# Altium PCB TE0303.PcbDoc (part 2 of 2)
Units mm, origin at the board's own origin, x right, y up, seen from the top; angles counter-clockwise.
Board outline 115 x 70 mm, 4 copper layers (L 01 (Top), L 02, L 03, L 04 (Bot)), stack 1.564 mm thick; 42 components, 141 nets, 429 pads, 134 vias.
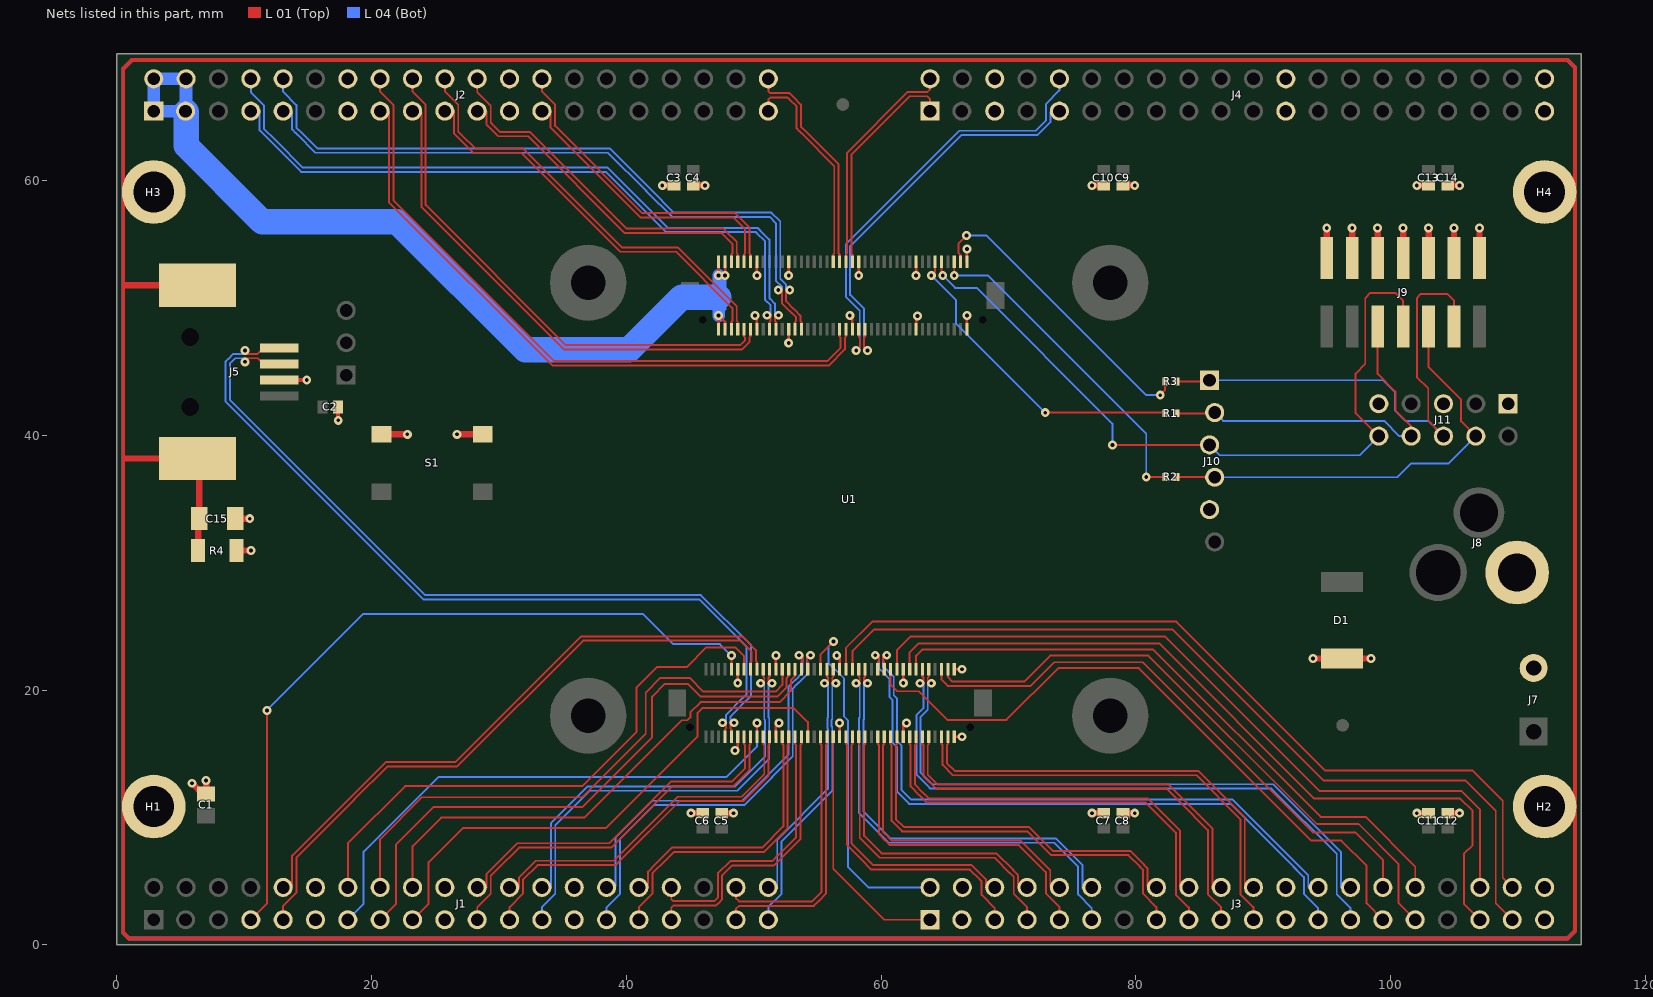
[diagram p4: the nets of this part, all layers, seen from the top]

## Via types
v1: diameter 0.7, hole 0.3, L 01 (Top) to L 04 (Bot), 134 vias

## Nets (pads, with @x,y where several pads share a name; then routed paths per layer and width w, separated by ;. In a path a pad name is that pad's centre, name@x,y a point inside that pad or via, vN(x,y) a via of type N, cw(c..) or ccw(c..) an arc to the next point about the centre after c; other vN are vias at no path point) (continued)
B0_L23_N: J2.9 U1.J4-25 | length 52.7
  L 01 (Top) w0.15: v1(51.93,51.429) 52.21,51.429 52.21,50.409 52.885,49.734 52.984,49.635 53.33,49.289 53.33,49.005 53.25,48.925 U1.J4-25@53.25,48.35
  L 04 (Bot) w0.15: J2.9@13.05,65.48 13.695,65.48 13.75,65.425 13.75,64.05 14.05,63.75 14.15,63.65 15.59,62.21 38.559,62.21 41.56,59.209 41.659,59.11 43.594,57.175 51.25,57.175 51.75,56.675 51.75,52.175 52.21,51.715 52.21,51.429 v1(51.93,51.429)
B0_L23_P: J2.10 U1.J4-27 | length 55
  L 01 (Top) w0.15: v1(52.83,51.429) 52.55,51.429 52.55,50.55 53.125,49.975 53.225,49.875 53.67,49.43 53.67,49.005 53.75,48.925 U1.J4-27@53.75,48.35
  L 04 (Bot) w0.15: J2.10@13.05,68.02 13.05,67 14.09,65.96 14.09,64.191 14.291,63.99 14.39,63.891 15.731,62.55 38.7,62.55 41.8,59.45 41.9,59.35 43.735,57.515 51.391,57.515 52.09,56.816 52.09,52.316 52.55,51.856 52.55,51.429 v1(52.83,51.429)
B0_L24_N: J2.7 U1.J4-17 | length 52.9
  L 01 (Top) w0.15: U1.J4-17@51.25,48.35 51.25,48.925 51.33,49.005 v1@51.33,49.45
  L 04 (Bot) w0.15: J2.7@10.51,65.48 11.195,65.48 11.2,65.475 11.2,63.975 12.175,63 12.275,62.9 14.465,60.71 38.384,60.71 43.119,55.975 50.175,55.975 50.25,55.9 50.9,55.25 50.9,50.65 51,50.55 51.05,50.5 51.33,50.22 51.33,49.45 v1(51.05,49.45)
B0_L24_P: J2.8 U1.J4-19 | length 55.2
  L 01 (Top) w0.15: v1@51.67,49.45 51.67,49.005 51.75,48.925 U1.J4-19@51.75,48.35
  L 04 (Bot) w0.15: J2.8@10.51,68.02 10.51,66.965 11.54,65.935 11.54,64.116 12.416,63.24 12.515,63.141 14.606,61.05 38.525,61.05 43.26,56.315 50.316,56.315 50.415,56.215 50.49,56.141 51.24,55.391 51.24,50.791 51.29,50.741 51.67,50.361 51.67,49.45 v1(51.95,49.45)
B2_GCLK13: J3.1 U1.J5-41 | length 19.6
  L 01 (Top) w0.15: U1.J5-41@56.25,16.35 56.25,5.975 60.245,1.98 J3.1@63.85,1.98
B2_GCLK_L13_N: J3.7 U1.J5-49 | length 25.2
  L 01 (Top) w0.15: U1.J5-49@58.25,16.35 58.25,15.775 58.33,15.695 ; 58.33,15.72 58.33,15.695 ; J3.7@71.47,1.98 71.47,2.98 70.425,4.025 70.425,5.35 70.225,5.55 70.125,5.65 68.925,6.85 59.9,6.85 59.8,6.95 58.33,8.42 58.33,15.695
B2_GCLK_L13_P: J3.8 U1.J5-51 | length 22.8
  L 01 (Top) w0.15: U1.J5-51@58.75,16.35 58.75,15.775 58.67,15.695 58.67,8.561 60.041,7.19 69.066,7.19 70.366,5.89 70.465,5.791 70.765,5.491 70.765,4.56 70.805,4.52 J3.8@71.47,4.52
B2_IO_L03: J1.15 U1.J5-28 | length 46.4
  L 01 (Top) w0.15: J1.15@20.67,1.98 21.925,3.235 21.925,7.9 24.875,10.85 36.575,10.85 42.025,16.3 42.025,19.5 43.025,20.5 44.825,20.5 45.374,19.951 45.825,19.5 51.85,19.5 52.59,20.24 52.59,20.965 52.75,21.125 U1.J5-28@52.75,21.65
B2_IO_P9: J3.29 U1.J5-60 | length 52.6
  L 01 (Top) w0.15: U1.J5-60@60.75,21.65 60.75,20.45 61.275,19.925 62.95,19.925 65.2,17.675 69.85,17.675 73.925,21.75 80.25,21.75 93.8,8.2 96.15,8.2 98.125,6.225 98.125,3.265 J3.29@99.41,1.98
B2_IO_P10: J3.35 U1.J5-66 | length 60.6
  L 01 (Top) w0.15: U1.J5-66@62.25,21.65 62.25,22.975 62.95,23.675 81.85,23.675 94.025,11.5 105.475,11.5 106.45,10.525 106.45,7.825 105.775,7.15 105.775,3.235 J3.35@107.03,1.98
B2_IO_R9: J3.32 U1.J5-68 | length 49.2
  L 01 (Top) w0.15: U1.J5-68@62.75,21.65 62.75,22.725 63.225,23.2 81.375,23.2 94.525,10.05 98.05,10.05 101.95,6.15 J3.32@101.95,4.52
B2_IO_R11: J3.36 U1.J5-62 | length 59.5
  L 01 (Top) w0.15: U1.J5-62@61.25,21.65 61.25,23.15 62.325,24.225 82.3,24.225 94.425,12.1 105.575,12.1 107.03,10.645 J3.36@107.03,4.52
B2_IO_U5: J1.18 U1.J5-30 | length 40.1
  L 01 (Top) w0.15: J1.18@23.21,4.52 23.21,7.76 25.45,10 36.7,10 44.35,17.65 44.8,17.65 45.025,17.875 45.025,18.275 45.825,19.075 52.05,19.075 52.93,19.955 52.93,20.805 53.25,21.125 U1.J5-30@53.25,21.65
B2_IO_U6: J3.2 U1.J5-38 | length 28.2
  L 01 (Top) w0.15: U1.J5-38@55.25,21.65 55.25,22.825 56.25,23.825 v1(56.275,23.825)
  L 04 (Bot) w0.15: v1(56.275,23.825) 55.875,23.425 55.875,22.15 57.093,20.932 57.093,17.957 57.4,17.65 57.4,6.125 59.005,4.52 J3.2@63.85,4.52
B2_IO_U13: J3.31 U1.J5-78 | length 48.7
  L 01 (Top) w0.15: U1.J5-78@65.25,21.65 65.25,21.05 65.61,20.69 71.24,20.69 73.275,22.725 81,22.725 94.225,9.5 97.5,9.5 100.65,6.35 100.65,3.28 J3.31@101.95,1.98
B2_IO_V7: J1.17 U1.J5-33 | length 42.5
  L 01 (Top) w0.15: J1.17@23.21,1.98 24.475,3.245 24.475,6.5 27.175,9.2 38.425,9.2 45.6,16.375 45.6,18.225 46,18.625 53.125,18.625 54.25,17.5 U1.J5-33@54.25,16.35
B2_IP_T7: J3.38 U1.J5-46 | length 67.1
  L 01 (Top) w0.15: U1.J5-46@57.25,21.65 57.25,23.325 59.325,25.4 83.2,25.4 94.9,13.7 106.45,13.7 108.825,11.325 108.825,5.265 J3.38@109.57,4.52
B2_IP_U8: J3.37 U1.J5-48 | length 67.6
  L 01 (Top) w0.15: U1.J5-48@57.75,21.65 57.75,23.05 59.475,24.775 82.875,24.775 94.75,12.9 105.9,12.9 108.275,10.525 108.275,3.275 J3.37@109.57,1.98
B2_IP_V4: J1.13 U1.J5-17 | length 43.1
  L 01 (Top) w0.15: U1.J5-17@50.25,16.35 v1(50.25,17.425)
  L 04 (Bot) w0.15: J1.13@18.13,1.98 19.375,3.225 19.375,7.325 25.25,13.2 47.875,13.2 50.25,15.575 v1(50.25,17.425)
B2_IP_V14: J3.30 U1.J5-76 | length 45
  L 01 (Top) w0.15: U1.J5-76@64.75,21.65 64.75,20.825 65.225,20.35 71.75,20.35 73.6,22.2 80.55,22.2 93.925,8.825 97.275,8.825 99.41,6.69 J3.30@99.41,4.52
B2_L04_N: J1.32 U1.J5-25 | length 21.1
  L 01 (Top) w0.15: J1.32@40.99,4.52 40.995,4.525 41.71,4.525 41.71,5.766 42.285,6.341 42.384,6.44 43.584,7.64 50.659,7.64 52.33,9.311 52.33,15.695 52.25,15.775 U1.J5-25@52.25,16.35
B2_L04_P: J1.31 U1.J5-27 | length 23.4
  L 01 (Top) w0.15: J1.31@40.99,1.98 40.99,2.965 42.05,4.025 42.05,5.625 42.525,6.1 42.625,6.2 43.725,7.3 50.8,7.3 52.67,9.17 52.67,15.695 52.75,15.775 U1.J5-27@52.75,16.35
B2_L05_N: J1.33 U1.J5-31 | length 22.5
  L 01 (Top) w0.15: J1.33@43.53,1.98 43.53,2.93 43.7,3.1 46.225,3.1 47.05,3.1 47.15,3.2 47.2,3.25 47.525,3.575 47.525,5.475 48.3,6.25 51.6,6.25 52.15,6.8 52.25,6.9 53.67,8.32 53.67,15.695 53.75,15.775 U1.J5-31@53.75,16.35
B2_L05_P: J1.34 U1.J5-29 | length 21.9
  L 01 (Top) w0.15: J1.34@43.53,4.52 43.53,3.61 43.7,3.44 46.225,3.44 46.909,3.44 46.959,3.49 47.185,3.716 47.185,5.616 48.159,6.59 51.459,6.59 51.91,7.041 52.009,7.14 53.33,8.461 53.33,15.695 53.25,15.775 U1.J5-29@53.25,16.35
B2_L06_N: J1.29 U1.J5-34 | length 32.8
  L 01 (Top) w0.15: v1@54.17,22.75 54.17,22.305 54.25,22.225 U1.J5-34@54.25,21.65
  L 04 (Bot) w0.15: J1.29@38.45,1.98 38.45,2.95 39.49,3.99 39.49,8.305 42.17,10.985 49.241,10.985 51.441,13.185 51.54,13.284 53.065,14.809 53.065,20.134 53.391,20.46 53.49,20.559 54.17,21.239 54.17,22.75 v1(54.45,22.75)
B2_L06_P: J1.30 U1.J5-32 | length 30.5
  L 01 (Top) w0.15: U1.J5-32@53.75,21.65 53.75,22.225 53.83,22.305 v1@53.83,22.75
  L 04 (Bot) w0.15: J1.30@38.45,4.52 39.07,4.52 39.15,4.6 39.15,8.445 42.03,11.325 49.1,11.325 51.2,13.425 51.3,13.525 52.725,14.95 52.725,20.275 53.15,20.7 53.25,20.8 53.83,21.38 53.83,22.75 v1(53.55,22.75)
B2_L07_N: J1.38 U1.J5-37 | length 20.2
  L 01 (Top) w0.15: J1.38@48.61,4.52 48.61,3.655 48.85,3.415 54.584,3.415 54.76,3.591 54.859,3.69 55.33,4.161 55.33,15.695 55.25,15.775 U1.J5-37@55.25,16.35
B2_L07_P: J1.37 U1.J5-39 | length 20.8
  L 01 (Top) w0.15: J1.37@48.61,1.98 48.61,2.835 48.85,3.075 54.725,3.075 55,3.35 55.1,3.45 55.67,4.02 55.67,15.695 55.75,15.775 U1.J5-39@55.75,16.35
B2_L09_N: J3.26 U1.J5-58 | length 49
  L 01 (Top) w0.15: v1@60.17,22.75 60.17,22.305 60.25,22.225 U1.J5-58@60.25,21.65
  L 04 (Bot) w0.15: v1(60.45,22.75) 60.17,22.75 60.17,21.88 60.525,21.525 60.625,21.425 61,21.05 61,19.625 61.25,19.375 61.25,16.025 61.6,15.675 61.6,12.175 62.35,11.425 87.6,11.425 92.525,6.5 93.55,5.475 93.55,4.575 93.605,4.52 J3.26@94.33,4.52
B2_L09_P: J3.25 U1.J5-56 | length 52
  L 01 (Top) w0.15: U1.J5-56@59.75,21.65 59.75,22.225 59.83,22.305 v1@59.83,22.75
  L 04 (Bot) w0.15: v1(59.55,22.75) 59.83,22.75 59.83,21.739 60.285,21.284 60.384,21.185 60.66,20.909 60.66,19.484 60.91,19.234 60.91,15.885 61.26,15.535 61.26,12.034 62.209,11.085 87.459,11.085 92.005,6.539 ; 92.285,6.26 92.005,6.539 ; 92.384,6.16 93.21,5.334 93.21,4.015 94.33,2.895 J3.25@94.33,1.98 ; 92.646,5.898 92.005,6.539
B2_L10_N: J3.5 U1.J5-45 | length 23.7
  L 01 (Top) w0.15: U1.J5-45@57.25,16.35 57.25,15.775 57.33,15.695 57.33,7.845 58.3,6.875 58.4,6.775 59.25,5.925 66.975,5.925 67.75,5.15 67.85,5.05 67.9,5 67.9,3.925 68.93,2.895 J3.5@68.93,1.98
B2_L10_P: J3.6 U1.J5-47 | length 21.4
  L 01 (Top) w0.15: U1.J5-47@57.75,16.35 57.75,15.775 57.67,15.695 57.67,7.986 58.541,7.115 58.64,7.016 59.391,6.265 67.116,6.265 67.991,5.39 68.09,5.291 68.25,5.131 68.25,4.6 68.33,4.52 J3.6@68.93,4.52
B2_L18_N: J3.9 U1.J5-55 | length 26.2
  L 01 (Top) w0.15: U1.J5-55@59.75,16.35 59.75,15.775 59.83,15.695 59.83,8.72 60.35,8.2 60.45,8.1 60.7,7.85 70.825,7.85 72.95,5.725 72.95,4.05 74.01,2.99 J3.9@74.01,1.98
B2_L18_P: J3.10 U1.J5-57 | length 23.9
  L 01 (Top) w0.15: U1.J5-57@60.25,16.35 60.25,15.775 60.17,15.695 60.17,8.861 60.591,8.44 60.69,8.341 60.841,8.19 70.966,8.19 73.29,5.866 73.29,4.59 73.36,4.52 J3.10@74.01,4.52
B2_L19_N: J3.17 U1.J5-65 | length 33.5
  L 01 (Top) w0.15: U1.J5-65@62.25,16.35 62.25,15.775 62.33,15.695 62.33,12.445 63.05,11.725 63.15,11.625 63.6,11.175 80.8,11.175 83.15,8.825 83.15,3.95 84.17,2.93 J3.17@84.17,1.98
B2_L19_P: J3.18 U1.J5-67 | length 31.2
  L 01 (Top) w0.15: U1.J5-67@62.75,16.35 62.75,15.775 62.67,15.695 62.67,12.586 63.291,11.965 63.39,11.866 63.741,11.515 80.941,11.515 83.49,8.966 83.49,4.59 83.56,4.52 J3.18@84.17,4.52
B2_L20_N: J3.15 U1.J5-59 | length 32.4
  L 01 (Top) w0.15: U1.J5-59@60.75,16.35 60.75,15.775 60.83,15.695 ; 60.83,15.72 60.83,15.695 ; J3.15@81.63,1.98 81.63,2.97 80.575,4.025 80.575,5.9 80.45,6.025 80.35,6.125 79.425,7.05 73.35,7.05 72.9,7.5 72.8,7.6 71.475,8.925 61.65,8.925 60.83,9.745 60.83,15.695
B2_L20_P: J3.16 U1.J5-61 | length 30
  L 01 (Top) w0.15: U1.J5-61@61.25,16.35 61.25,15.775 61.17,15.695 61.17,9.886 61.791,9.265 71.616,9.265 73.041,7.84 73.14,7.741 73.491,7.39 79.566,7.39 80.591,6.365 80.69,6.266 80.915,6.041 80.915,4.56 80.955,4.52 J3.16@81.63,4.52
B2_L21_N: J3.27 U1.J5-70 | length 50.2
  L 01 (Top) w0.15: U1.J5-70@63.25,21.65 63.25,21.075 63.33,20.995 v1@63.33,20.55
  L 04 (Bot) w0.15: v1(63.05,20.55) 63.33,20.55 63.33,18.605 62.775,18.05 62.775,13.394 63.56,12.609 63.659,12.51 63.884,12.285 90.659,12.285 95.785,7.159 95.785,6.025 ; 95.785,6.25 95.785,3.965 96.87,2.88 J3.27@96.87,1.98
B2_L21_P: J3.28 U1.J5-72 | length 47.8
  L 01 (Top) w0.15: v1@63.67,20.55 63.67,20.995 63.75,21.075 U1.J5-72@63.75,21.65
  L 04 (Bot) w0.15: v1(63.95,20.55) 63.67,20.55 63.67,18.464 63.115,17.909 63.115,13.535 63.8,12.85 63.9,12.75 64.025,12.625 90.8,12.625 96.125,7.3 96.125,6.025 96.125,4.525 96.13,4.52 J3.28@96.87,4.52
B2_L22_N: J3.19 U1.J5-69 | length 34.7
  L 01 (Top) w0.15: U1.J5-69@63.25,16.35 63.25,15.775 63.33,15.695 63.33,13.245 64.325,12.25 82.45,12.25 83.35,11.35 83.45,11.25 85.675,9.025 85.675,4 86.71,2.965 J3.19@86.71,1.98
B2_L22_P: J3.20 U1.J5-71 | length 32.4
  L 01 (Top) w0.15: U1.J5-71@63.75,16.35 63.75,15.775 63.67,15.695 63.67,13.386 64.466,12.59 82.591,12.59 83.591,11.59 83.69,11.491 86.015,9.166 86.015,4.56 86.055,4.52 J3.20@86.71,4.52
B2_L24_N: J3.22 U1.J5-77 | length 33.5
  L 01 (Top) w0.15: U1.J5-77@65.25,16.35 65.25,15.775 65.17,15.695 65.17,14.286 65.791,13.665 84.916,13.665 88.391,10.19 88.465,10.115 88.565,10.016 88.565,4.52 88.565,4.485 88.6,4.52 J3.22@89.25,4.52
B2_L24_P: J3.21 U1.J5-75 | length 35.7
  L 01 (Top) w0.15: U1.J5-75@64.75,16.35 64.75,15.775 64.83,15.695 64.83,14.145 65.65,13.325 84.775,13.325 88.15,9.95 88.225,9.875 88.225,4 89.25,2.975 J3.21@89.25,1.98
B2B_D_N: J5.2 U1.J5-9 | length 65.5
  L 01 (Top) w0.15: v1(10.045,45.795) 10.045,46.075 11.05,46.075 11.5,45.625 J5.2@12.75,45.625 ; U1.J5-9@48.25,16.35 48.25,16.925 48.17,17.005 48.17,17.45 v1(48.45,17.45)
  L 04 (Bot) w0.15: 9.575,46.075 v1@10.045,46.075 ; v1(10.045,45.795) v1@10.045,46.075 ; v1(48.45,17.45) 48.17,17.45 48.17,17.939 48.635,18.404 49.391,19.16 49.49,19.259 49.79,19.559 49.79,23.547 45.862,27.475 35.475,27.475 24.2,27.475 8.875,42.8 8.875,45.675 8.975,45.775 9.275,46.075 v1@10.045,46.075
B2B_D_P: J5.3 U1.J5-7 | length 65.6
  L 01 (Top) w0.15: v1(10.045,46.695) 10.045,46.415 11.04,46.415 11.5,46.875 J5.3@12.75,46.875 ; v1(47.55,17.45) 47.83,17.45 47.83,17.005 47.75,16.925 U1.J5-7@47.75,16.35
  L 04 (Bot) w0.15: v1(10.045,46.695) 10.045,46.415 9.134,46.415 8.734,46.015 8.635,45.916 8.535,45.816 8.535,42.659 24.059,27.135 35.475,27.135 45.721,27.135 49.45,23.406 49.45,19.7 49.25,19.5 49.15,19.4 47.83,18.08 47.83,17.45 v1(47.55,17.45)
B3_IO_L18N: J1.16 U1.J5-26 | length 44.4
  L 01 (Top) w0.15: J1.16@20.67,4.52 20.67,8.32 23.95,11.6 36.525,11.6 41.525,16.6 41.525,19.825 42.675,20.975 44.975,20.975 46.05,19.9 51.725,19.9 52.25,20.425 U1.J5-26@52.25,21.65
B3_IO_T2: J1.14 U1.J5-14 | length 44.3
  L 01 (Top) w0.15: J1.14@18.13,4.52 18.13,7.98 22.625,12.475 36.525,12.475 40.8,16.75 40.8,20.225 42.4,21.825 44.725,21.825 46.275,23.375 48.55,23.375 49.25,22.675 U1.J5-14@49.25,21.65
B3_L01_N: J2.20 U1.J4-7 | length 34
  L 01 (Top) w0.15: J2.20@25.75,68.02 25.75,67.025 26.8,65.975 26.8,63.875 26.975,63.7 27.075,63.6 28.125,62.55 31.875,62.55 37.525,56.9 37.625,56.8 39.65,54.775 44.05,54.775 48.67,50.155 48.67,49.005 48.75,48.925 U1.J4-7@48.75,48.35
B3_L01_P: J2.19 U1.J4-5 | length 31.7
  L 01 (Top) w0.15: J2.19@25.75,65.48 26.45,65.48 26.46,65.49 26.46,65.48 26.46,63.734 26.735,63.459 26.834,63.36 27.984,62.21 31.734,62.21 37.285,56.659 37.384,56.56 39.509,54.435 43.909,54.435 48.33,50.014 48.33,49.005 48.25,48.925 U1.J4-5@48.25,48.35
B3_L02_N: J2.17 U1.J4-11 | length 39.8
  L 01 (Top) w0.15: J2.17@23.21,65.48 23.845,65.48 23.9,65.425 23.9,57.975 35.1,46.775 49.1,46.775 49.2,46.875 49.3,46.975 49.67,47.345 49.67,47.695 49.75,47.775 U1.J4-11@49.75,48.35
B3_L02_P: J2.18 U1.J4-9 | length 41
  L 01 (Top) w0.15: J2.18@23.21,68.02 23.21,67.015 24.24,65.985 24.24,58.116 35.241,47.115 48.959,47.115 49.059,47.215 49.33,47.486 49.33,47.695 49.25,47.775 U1.J4-9@49.25,48.35
B3_L03_N: J2.25 U1.J4-10 | length 23.2
  L 01 (Top) w0.15: J2.25@33.37,65.48 34.05,65.48 34.06,65.49 34.06,65.48 34.06,64.184 41.109,57.135 48.409,57.135 49.33,56.214 49.33,54.305 49.25,54.225 U1.J4-10@49.25,53.65
B3_L03_P: J2.26 U1.J4-12 | length 25.4
  L 01 (Top) w0.15: J2.26@33.37,68.02 33.37,67.03 34.4,66 34.4,64.325 41.25,57.475 48.55,57.475 49.67,56.355 49.67,54.305 49.75,54.225 U1.J4-12@49.75,53.65
B3_L07_N: J2.22 U1.J4-8 | length 28.7
  L 01 (Top) w0.15: J2.22@28.29,68.02 28.29,66.96 29.35,65.9 29.35,64.575 29.375,64.55 29.475,64.45 30.075,63.85 32.425,63.85 40.025,56.25 47.625,56.25 47.725,56.15 47.825,56.05 48.67,55.205 48.67,54.305 48.75,54.225 U1.J4-8@48.75,53.65
B3_L07_P: J2.21 U1.J4-6 | length 26.4
  L 01 (Top) w0.15: J2.21@28.29,65.48 28.97,65.48 29.01,65.44 29.01,64.434 29.135,64.309 29.234,64.21 29.934,63.51 32.284,63.51 39.884,55.91 47.484,55.91 ; 47.485,55.909 47.584,55.81 48.33,55.064 48.33,54.305 48.25,54.225 U1.J4-6@48.25,53.65
B3_L17_N: J1.40 U1.J5-40 | length 19.9
  L 01 (Top) w0.15: U1.J5-40@55.75,21.65 55.75,21.075 55.83,20.995 v1@55.83,20.55
  L 04 (Bot) w0.15: J1.40@51.15,4.52 51.17,4.5 51.85,4.5 51.85,4.52 51.85,8.275 55.83,12.255 55.83,16.983 55.783,17.03 55.783,17.808 55.83,17.856 55.83,20.55 v1(55.55,20.55)
B3_L17_P: J1.39 U1.J5-42 | length 22.1
  L 01 (Top) w0.15: v1@56.17,20.55 56.17,20.995 56.25,21.075 U1.J5-42@56.25,21.65
  L 04 (Bot) w0.15: J1.39@51.15,1.98 51.15,3 52.19,4.04 52.19,8.134 56.17,12.114 56.17,17.124 56.123,17.171 56.123,17.667 56.17,17.715 56.17,20.55 v1(56.45,20.55)
B3_L19_N: J3.12 U1.J5-52 | length 33
  L 01 (Top) w0.15: v1@58.67,20.55 58.67,20.995 58.75,21.075 U1.J5-52@58.75,21.65
  L 04 (Bot) w0.15: v1(58.95,20.55) 58.67,20.55 58.67,17.715 58.623,17.668 58.623,10.483 60.741,8.365 73.741,8.365 75.441,6.665 75.54,6.566 75.815,6.291 75.815,4.52 75.815,4.45 76.48,4.45 J3.12@76.55,4.52
B3_L19_P: J3.11 U1.J5-50 | length 35.2
  L 01 (Top) w0.15: U1.J5-50@58.25,21.65 58.25,21.075 58.33,20.995 v1@58.33,20.55
  L 04 (Bot) w0.15: v1(58.05,20.55) 58.33,20.55 58.33,17.856 58.283,17.808 58.283,10.342 60.6,8.025 73.6,8.025 75.2,6.425 75.3,6.325 75.475,6.15 75.475,3.975 76.55,2.9 J3.11@76.55,1.98
B3_L20_N: J1.23 U1.J5-21 | length 29.4
  L 01 (Top) w0.15: J1.23@30.83,1.98 30.83,2.98 31.9,4.05 31.9,5.15 33.025,6.275 39.15,6.275 39.35,6.475 39.45,6.575 44.175,11.3 49.2,11.3 51.17,13.27 51.17,15.695 51.25,15.775 U1.J5-21@51.25,16.35
B3_L20_P: J1.24 U1.J5-19 | length 27.2
  L 01 (Top) w0.15: J1.24@30.83,4.52 30.875,4.475 31.56,4.475 31.56,4.52 31.56,5.291 32.884,6.615 39.009,6.615 39.11,6.716 39.209,6.815 44.034,11.64 49.059,11.64 50.83,13.411 50.83,15.695 50.75,15.775 U1.J5-19@50.75,16.35
B3_L21_N: J1.9 U1.J5-16 | length 49.9
  L 01 (Top) w0.15: J1.9@13.05,1.98 13.05,3.075 14.1,4.125 14.1,6.875 18.55,11.325 18.65,11.425 21.25,14.025 26.725,14.025 36.6,23.9 48.95,23.9 49.83,23.02 49.83,22.305 49.75,22.225 U1.J5-16@49.75,21.65
B3_L21_P: J1.10 U1.J5-18 | length 48.8
  L 01 (Top) w0.15: J1.10@13.05,4.52 13.645,4.52 J1.10@13.76,4.635 ; J1.10@13.76,4.52 13.76,7.016 21.109,14.365 26.584,14.365 36.459,24.24 49.091,24.24 50.17,23.161 50.17,22.305 50.25,22.225 U1.J5-18@50.25,21.65
B3_L22_N: J1.21 U1.J5-15 | length 30.3
  L 01 (Top) w0.15: J1.21@28.29,1.98 28.29,2.965 29.35,4.025 29.35,5.425 29.775,5.85 29.875,5.95 31.575,7.65 38.8,7.65 43.65,12.5 48.45,12.5 48.65,12.7 48.75,12.8 49.67,13.72 49.67,15.695 49.75,15.775 U1.J5-15@49.75,16.35
B3_L22_P: J1.22 U1.J5-13 | length 28
  L 01 (Top) w0.15: J1.22@28.29,4.52 28.295,4.525 29.01,4.525 29.01,5.566 29.535,6.091 29.634,6.19 31.434,7.99 38.659,7.99 43.509,12.84 48.309,12.84 48.41,12.941 48.509,13.04 49.33,13.861 49.33,15.695 49.25,15.775 U1.J5-13@49.25,16.35
B3_L23_N: J1.26 U1.J5-20 | length 31.9
  L 01 (Top) w0.15: U1.J5-20@50.75,21.65 50.75,21.075 50.83,20.995 v1@50.83,20.55
  L 04 (Bot) w0.15: J1.26@33.37,4.52 33.39,4.5 34.075,4.5 34.075,4.52 34.075,9.55 36.975,12.45 48.55,12.45 50.882,14.782 50.882,17.662 50.83,17.715 50.83,20.55 v1(50.55,20.55)
B3_L23_P: J1.25 U1.J5-22 | length 34.2
  L 01 (Top) w0.15: v1@51.17,20.55 51.17,20.995 51.25,21.075 U1.J5-22@51.25,21.65
  L 04 (Bot) w0.15: J1.25@33.37,1.98 33.37,2.97 34.415,4.015 34.415,9.409 37.116,12.11 48.691,12.11 51.222,14.642 51.222,17.803 51.17,17.856 51.17,20.55 v1(51.45,20.55)
FGND: C15.1 H1.1 H2.1 H3.1 H4.1 J5.S1 J5.S2 R4.1 | length 748.1
  L 01 (Top) w0.3: 0.5,0.95 0.95,0.5 113.9,0.5 114.5,1.1 114.5,10.87 114.5,59.13 114.5,68.9 113.9,69.5 1.175,69.5 0.5,68.825 0.5,59.13 0.5,10.87 0.5,0.95
  L 01 (Top) w0.5: 0.59,38.2 J5.S1@6.33,38.2 6.475,38.055 C15.1@6.475,33.475 6.375,33.375 R4.1@6.375,30.975 ; 0.59,51.8 J5.S2@6.33,51.8
  L 04 (Bot) w0.3: 0.5,0.95 0.95,0.5 113.9,0.5 114.5,1.1 114.5,10.87 114.5,59.13 114.5,68.9 113.9,69.5 1.175,69.5 0.5,68.825 0.5,59.13 0.5,10.87 0.5,0.95
GCLK_L11_N: J4.2 U1.J4-42 | length 18
  L 01 (Top) w0.15: U1.J4-42@57.25,53.65 57.25,54.225 57.33,54.305 57.33,62.211 62.109,66.99 63.65,66.99 63.85,67.19 J4.2@63.85,68.02
GCLK_L11_P: J4.1 U1.J4-44 | length 17.6
  L 01 (Top) w0.15: U1.J4-44@57.75,53.65 57.75,54.225 57.67,54.305 57.67,62.07 62.25,66.65 63.63,66.65 63.85,66.43 J4.1@63.85,65.48
GCLK_L12_N: J4.9 U1.J4-47 | length 32.2
  L 01 (Top) w0.15: U1.J4-47@58.75,48.35 58.75,47.775 58.67,47.695 58.67,46.675 v1(58.95,46.675)
  L 04 (Bot) w0.15: v1(58.95,46.675) 58.67,46.675 58.67,49.955 57.575,51.05 57.575,51.9 57.575,54.875 66.3,63.6 72.275,63.6 73.1,64.425 73.2,64.525 73.3,64.625 73.3,65.4 73.38,65.48 J4.9@74.01,65.48
GCLK_L12_P: J4.10 U1.J4-45 | length 34.5
  L 01 (Top) w0.15: v1(58.05,46.675) 58.33,46.675 58.33,47.695 58.25,47.775 U1.J4-45@58.25,48.35
  L 04 (Bot) w0.15: v1(58.05,46.675) 58.33,46.675 58.33,49.814 57.235,50.909 57.235,51.9 57.235,55.016 66.159,63.94 72.134,63.94 72.86,64.666 72.959,64.765 ; 72.96,64.766 72.96,66.06 74.01,67.11 J4.10@74.01,68.02
GCLK_L13_N: J2.15 U1.J4-41 | length 51.1
  L 01 (Top) w0.15: J2.15@20.67,65.48 21.345,65.48 21.36,65.465 21.36,58.334 34.184,45.51 55.916,45.51 57.17,46.764 57.17,47.695 57.25,47.775 U1.J4-41@57.25,48.35
GCLK_L13_P: J2.16 U1.J4-39 | length 52.2
  L 01 (Top) w0.15: J2.16@20.67,68.02 20.67,67.005 21.7,65.975 21.7,58.475 34.325,45.85 55.775,45.85 56.83,46.905 56.83,47.695 56.75,47.775 U1.J4-39@56.75,48.35
GCLK_L14_N: J2.39 U1.J4-38 | length 17
  L 01 (Top) w0.15: J2.39@51.15,65.48 51.15,66.4 51.3,66.55 52.675,66.55 52.75,66.475 52.85,66.375 53.375,65.85 53.375,64.125 53.625,63.875 53.725,63.775 56.33,61.17 56.33,54.305 56.25,54.225 U1.J4-38@56.25,53.65
GCLK_L14_P: J2.40 U1.J4-40 | length 17.6
  L 01 (Top) w0.15: J2.40@51.15,68.02 51.15,67.04 51.3,66.89 52.816,66.89 52.991,66.715 53.09,66.616 53.715,65.991 53.715,64.266 53.866,64.115 53.965,64.016 56.67,61.311 56.67,54.305 56.75,54.225 U1.J4-40@56.75,53.65
GND: C1.1 C2.2 C3.2 C4.2 C5.2 C6.2 C7.2 C8.2 C9.2 C10.2 C11.2 C12.2 C13.2 C14.2 C15.2 D1.2 J1.11 J1.12 J1.19 J1.20 J1.27 J1.28 J2.13 J2.14 J2.23 J2.24 J3.3 J3.4 J3.23 J3.24 J3.39 J3.40 J4.5 J4.6 J4.23 J4.24 J4.39 J4.40 J5.4 J7.2 J8.3 J9.1 J9.3 J9.5 J9.7 J9.9 J9.11 J9.13 J10.5 J11.1 J11.5 J11.9 R4.2 S1.2 U1.J4-13 U1.J4-14 U1.J4-23 U1.J4-24 U1.J4-43 U1.J4-46 U1.J4-63 U1.J4-64 U1.J4-79 U1.J4-80 U1.J5-11 U1.J5-12 U1.J5-23 U1.J5-24 U1.J5-43 U1.J5-44 U1.J5-63 U1.J5-64 U1.J5-79 U1.J5-80 | length 65
  L 01 (Top) w0.2: v1(48.525,15.275) 48.75,15.5 U1.J5-11@48.75,16.35 ; v1(48.75,20.575) U1.J5-12@48.75,21.65 ; v1(50.1,49.425) 50.25,49.275 U1.J4-13@50.25,48.35 ; v1(50.25,52.575) U1.J4-14@50.25,53.65 ; U1.J5-23@51.75,16.35 v1@51.75,17.425 ; U1.J5-24@51.75,21.65 v1(51.75,22.725) ; v1(52.75,47.275) U1.J4-23@52.75,48.35 ; v1(52.75,52.575) U1.J4-24@52.75,53.65 ; U1.J5-43@56.75,16.35 v1(56.75,17.425) ; U1.J5-44@56.75,21.65 v1@56.75,22.725 ; U1.J4-43@57.75,48.35 v1@57.75,49.425 ; v1(58.25,52.575) U1.J4-46@58.25,53.65 ; U1.J5-63@61.75,16.35 v1@61.75,17.425 ; v1(61.75,20.575) U1.J5-64@61.75,21.65 ; U1.J4-63@62.75,48.35 v1@62.75,49.425 ; v1(62.75,52.575) U1.J4-64@62.75,53.65 ; U1.J5-79@65.75,16.35 v1(66.35,16.35) ; U1.J5-80@65.75,21.65 v1(66.35,21.65) ; U1.J4-79@66.75,48.35 v1(66.75,49.425) ; U1.J4-80@66.75,53.575 v1(66.75,54.65)
  L 01 (Top) w0.3: J5.4@12.75,44.375 v1(14.9,44.375) ; C2.2@17.35,42.25 17.35,41.225 v1(17.375,41.2)
  L 01 (Top) w0.5: v1(5.9,12.7) 6.75,11.85 C1.1@7,11.85 v1(7,12.925) ; C15.2@9.275,33.475 v1(10.425,33.475) ; R4.2@9.375,30.975 v1(10.525,30.975) ; S1.2@20.775,40.1 v1(22.8,40.1) ; v1(26.7,40.1) S1.2@28.725,40.1 ; v1(42.825,59.65) C3.2@43.75,59.65 ; v1(45.075,10.35) C6.2@46,10.35 ; C4.2@45.25,59.65 v1(46.175,59.65) ; C5.2@47.5,10.35 v1(48.425,10.35) ; v1(76.575,10.35) C7.2@77.5,10.35 ; v1(76.575,59.65) C10.2@77.5,59.65 ; C8.2@79,10.35 v1(79.925,10.35) ; C9.2@79,59.65 v1(79.925,59.65) ; v1(93.925,22.5) v1(98.475,22.5) ; J9.13@95,53.935 v1(95,56.3) ; J9.11@97,53.935 v1(97,56.3) ; J9.9@99,53.935 v1(99,56.3) ; J9.7@101,53.935 v1(101,56.3) ; v1(102.075,10.35) C11.2@103,10.35 ; v1(102.075,59.65) C13.2@103,59.65 ; J9.5@103,53.935 v1(103,56.3) ; C12.2@104.5,10.35 v1(105.425,10.35) ; C14.2@104.5,59.65 v1(105.425,59.65) ; J9.3@105,53.935 v1(105,56.3) ; J9.1@107,53.935 v1(107,56.3)
  other v1: 52,17.425 62,17.425 56.525,22.725 62.875,49.4 57.55,49.425
NetR1_1: R1.1 U1.J4-70 | length 25.1
  L 01 (Top) w0.15: v1(63.95,52.575) 64.25,52.875 U1.J4-70@64.25,53.65 ; v1(72.9,41.8) 82.25,41.8 R1.1@82.3,41.75
  L 04 (Bot) w0.15: v1(63.95,52.575) 65.875,50.65 65.875,48.825 v1(72.9,41.8)
NetR2_1: R2.1 U1.J4-76 | length 26.2
  L 01 (Top) w0.15: v1(65.75,52.575) U1.J4-76@65.75,53.65 ; v1(80.825,36.75) R2.1@82.3,36.75
  L 04 (Bot) w0.15: v1(65.75,52.575) 68.4,52.575 80.825,40.15 v1(80.825,36.75)
NetR3_1: R3.1 U1.J4-78 | length 24
  L 01 (Top) w0.15: U1.J4-78@66.25,53.65 66.25,54.175 66.075,54.35 66.075,55.075 v1(66.725,55.725) ; v1(81.925,43.175) 82.3,43.55 R3.1@82.3,44.25
  L 04 (Bot) w0.15: v1(66.725,55.725) 68.275,55.725 80.825,43.175 v1(81.925,43.175)
RESET: J1.7 U1.J5-10 | length 59
  L 01 (Top) w0.15: J1.7@10.51,1.98 11.775,3.245 v1(11.775,18.425) ; U1.J5-10@48.25,21.65 v1(48.25,22.725)
  L 04 (Bot) w0.15: v1(11.775,18.425) 19.35,26 41.3,26 43.675,23.625 47.35,23.625 v1(48.25,22.725)
TCK: J9.6 J10.4 J11.4 R2.2 | length 35
  L 01 (Top) w0.15: R2.2@83.2,36.75 86.18,36.75 J10.4@86.2,36.73 ; J9.6@103,48.565 103,45.375 105.55,42.825 105.55,41.12 J11.4@106.71,39.96
  L 04 (Bot) w0.15: J10.4@86.2,36.73 100.53,36.73 101.625,37.825 104.575,37.825 J11.4@106.71,39.96
TDI: J9.10 J10.2 J11.8 R1.2 | length 28.9
  L 01 (Top) w0.15: R1.2@83.2,41.75 86.14,41.75 J10.2@86.2,41.81 ; J9.10@99,48.565 99,44.85 100.4,43.45 100.4,41.975 101.63,40.745 J11.8@101.63,39.96
  L 04 (Bot) w0.15: J10.2@86.2,41.81 86.86,41.15 99.525,41.15 100.715,39.96 J11.8@101.63,39.96
TDO: J9.8 J10.3 J11.10 U1.J4-72 | length 60.1
  L 01 (Top) w0.15: v1@64.75,52.575 U1.J4-72@64.75,53.65 ; v1(78.175,39.25) 85.78,39.25 J10.3@85.8,39.27 ; J11.10@99.09,39.96 97.275,41.775 97.275,44.875 98.025,45.625 98.025,50.8 98.425,51.2 100.4,51.2 101,50.6 J9.8@101,48.565
  L 04 (Bot) w0.15: v1(64.85,52.575) 65.825,51.6 67.525,51.6 78.175,40.95 v1(78.175,39.25) ; J10.3@85.8,39.27 86.61,38.46 97.59,38.46 J11.10@99.09,39.96
TMS: J9.4 J10.1 J11.6 R3.2 | length 40.7
  L 01 (Top) w0.15: R3.2@83.2,44.25 85.7,44.25 J10.1@85.8,44.35 ; J11.6@104.17,39.96 102.975,41.155 102.975,43.7 102.075,44.6 102.075,50.8 102.4,51.125 104.475,51.125 105,50.6 J9.4@105,48.565
  L 04 (Bot) w0.15: J10.1@85.8,44.35 99.425,44.35 100.375,43.4 100.375,41.95 101.175,41.15 102.98,41.15 J11.6@104.17,39.96
VCCIO0: J2.1 J2.2 J2.3 J2.4 U1.J4-1 U1.J4-2 U1.J4-3 U1.J4-4 | length 74
  L 01 (Top) w0.2: U1.J4-1@47.25,48.35 v1(47.25,49.425) 47.75,48.925 U1.J4-3@47.75,48.35 ; v1(47.25,52.575) U1.J4-2@47.25,53.65 ; v1(47.75,52.575) U1.J4-4@47.75,53.65
  L 04 (Bot) w0.2: v1(47.25,49.425) 47.75,49.925 v1(47.75,52.575)
  L 04 (Bot) w1: J2.3@5.425,65.45 5.395,65.48 J2.3@5.39,65.48 ; v1(47.25,49.425) 47.25,50.875 v1(47.25,52.575) ; J2.3@5.39,65.48 5.43,65.52 J2.4@5.43,68.02 J2.2@2.89,68.02 J2.1@2.89,65.48 J2.3@5.39,65.48
  L 04 (Bot) w2: J2.3@5.425,65.45 5.425,62.775 11.4,56.8 22,56.8 32.05,46.75 40.225,46.75 44.35,50.875 47.25,50.875
pads on no net: J4.35 J4.36 J4.37 J4.38 J5.A J5.B J8.2 J9.12 J9.14 J11.2 PM1.0 PM2.0 PM3.0 U1.1 U1.2 U1.3 U1.4 U1.A U1.B U1.G1 U1.G2
copper on no net: | length 89.8
  L 01 (Top) w0.15: 61.42,19.375 61.5,19.295 61.5,18.5 ; 61.84,18.5 61.84,19.295 61.92,19.375 ; 2.05,17.375 2.05,26.375 4.05,26.375 4.05,17.375 2.05,17.375
  L 02 w0.15: 2.05,17.375 4.05,17.375 4.05,26.375 2.05,26.375 2.05,17.375
  L 03 w0.15: 2.05,17.375 4.05,17.375 4.05,26.375 2.05,26.375 2.05,17.375
  L 04 (Bot) w0.15: 2.05,17.375 4.05,17.375 4.05,26.375 2.05,26.375 2.05,17.375

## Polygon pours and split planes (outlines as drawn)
GND on L 02 "L 02-No Net" (hatched 90Degree grid 0.14 track 0.15, remove dead copper, pour order 1000): 0,0 115,0 115,70 0,70
GND on L 03 "L 02-No Net" (hatched 90Degree grid 0.14 track 0.15, remove dead copper, pour order 1001): 0,0 115,0 115,70 0,70

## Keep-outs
Keep-Out Layer:
  the board outline again, w0.3

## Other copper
L 01 (Top):
  text "J2" at 5.125,62 h1.52
  text "J4" at 107.8,61.975 h1.52
  text "EXT" at 20.275,49.15 h1.52
  text "USB" at 20.325,43.9 h1.52
  text "TMS" at 88.5,43.5 h1.52
  text "TDI" at 88.5,41 h1.52
  text "TDO" at 88.5,38.5 h1.52
  text "RESET" at 13.55,37.125 h1.52
  text "TCK" at 88.5,36 h1.52
  text "GND" at 88.5,33.5 h1.52
  text "3.3V" at 88.5,31 h1.52
  text "TE0303-01 - 2010" at 47.225,26.8 h1.52
  text "L1" at 3.55,17.875 h1 r90
  text "+5V" at 101.575,15.625 h1.52
  text "J3" at 109.95,6.275 h1.52
  text "J1" at 4.35,6.25 h1.52
L 02:
  text "L2" at 3.55,19.875 h1 r90
L 03:
  text "L3" at 3.55,21.875 h1 r90
L 04 (Bot):
  text "L4" at 3.55,25.875 h1 r90

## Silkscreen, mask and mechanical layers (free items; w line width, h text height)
Top Solder:
  rectangle: 58.775,29.9 71.9,40.85
  region: 46.1,40.825 46.1,29.875 54.45,29.875 54.45,40.825
  rectangle: 4.825,61.625 8.05,63.925
  rectangle: 107.4,61.525 110.775,63.875
  rectangle: 109.6,6 112.875,8.1
  rectangle: 3.975,5.9 6.825,8.125
  rectangle: 13.05,36.625 21.075,39.125
  rectangle: 88,30.5 94.5,45.5
  rectangle: 19.9,48.775 24.725,51.075
  rectangle: 19.925,43.45 24.8,45.9
  rectangle: 101,15.225 106.325,17.65
  rectangle: 46.75,26.15 71.325,28.9
Boardumrandung:
  the board outline again, w0.01

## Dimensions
0,0 to 37,52 on Dimension
0,0 to 2.89,59.13 on Dimension
0,0 to 37,18 on Dimension
0,0 to 2.89,10.87 on Dimension
78,18 to 78,52 on Dimension
112.11,10.87 to 112.11,59.13 on Dimension
115,0 to 115,70 on Dimension
0,70 to 112.11,59.13 on Dimension
0,70 to 78,52 on Dimension
0,70.259 to 37,52 on Dimension
0,70 to 2.89,59.13 on Dimension
37,18 to 78,18 on Dimension
2.89,10.87 to 112.11,10.87 on Dimension
0,0 to 115,0 on Dimension
0,0 to 2.89,1.98 on Dimension1
0,70.254 to 2.89,65.48 on Dimension1
0,70 to 63.85,65.48 on Dimension1
0,70 to 2.89,65.48 on Dimension1
0,-0.254 to 63.85,1.98 on Dimension1
0,0 to 2.89,1.98 on Dimension1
